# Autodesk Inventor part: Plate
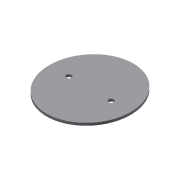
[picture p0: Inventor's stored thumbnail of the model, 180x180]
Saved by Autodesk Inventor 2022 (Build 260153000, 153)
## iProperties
Created: 2009-04
Part Number: Plate
Document SubType Name: Modeling
Designer: Sham
Density: 1 g/cm^3
Material: Generic
Appearance: Default
Author: Sham
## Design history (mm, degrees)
sketch "Sketch1"
  geometry: L1 (0, 0)-(0, 182.14); L2 (0, 0)-(192, 0); C1 r 6.25 at (-50, 0); C2 r 6.25 at (50, 0); 3 further points
  constraints: 4 end point, 3 point on line, 2 centre point, 1 coincident, 1 horizontal, 1 midpoint, 1 vertical, 5 other
  dimensions: "d1" = 12.5 diameter of C1; "d2" = 12.5 diameter of C2; "d3" = 100 distance of C2.centre C1.centre; "d4" = 102.5 distance of point (0, 0) point (0, 102.5); "d5" = 96 distance of point (96, 0) point (0, 0); "d6" = 50 distance of L1.start C1.centre
extrude "Extrusion1" new body sketch "Sketch1" distance "d7" = 6; taper "d8" = 0 deg
body "Solid1"
